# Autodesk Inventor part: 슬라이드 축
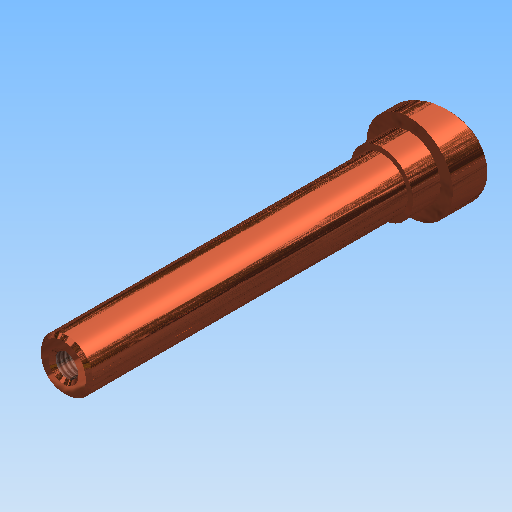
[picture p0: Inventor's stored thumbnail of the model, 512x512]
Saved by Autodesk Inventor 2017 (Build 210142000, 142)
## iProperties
Created: 2021-07
Part Number: 슬라이드 축
Document SubType Name: 모델링
Designer: mdu
Mass: 21.5729 g
Surface Area: 67.586 cm^2
Volume: 21.5729 cm^3
Density: 1 g/cm^3
Material: 일반
Appearance: 금속 1400F 열
변환 표준: STEP AP214IS
파일 이름: C:\Users\SeoGD\Desktop\?쒗뿕\異?stp
전처리기: Build: 253, Release: 2010 SP1 - Date: Wed 07/29/2009
전송 단위: 밀리미터
불확실성: 0.01
Author: mdu
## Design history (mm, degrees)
sketch "스케치1"
  geometry: L1 (0, 100)-(7.5, 100); L2 (7.5, 100)-(7.5, 0); L3 (7.5, 0)-(12.5, 0); L4 (12.5, 0)-(12.5, -17); L5 (12.5, -17)-(0, -17); L6 (0, -17)-(0, 100); 1 further point
  constraints: 12 end point, 2 parallel, 2 point on line, 1 perpendicular, 1 vertical
  dimensions: "d0" = 100 distance from line of L1 point (0, 0); "d1" = 15 diameter of L2 L6; "d2" = 25 diameter of L4 L6; "d3" = 17 distance of L3.end L4.end
revolve "회전1" sketch "스케치1" stored, may be unused: angle "d4" = 90 deg
sketch "스케치2"
  geometry: L1 (12.5, 0)-(12.5, -17) reference; L2 (-12.5, -17)-(12.5, -17) reference; L3 (-12.5, 0)-(-12.5, -17) reference; L4 (12.5, -5)-(-12.5, -11.699); L5 (-12.5, 0)-(12.5, 0) reference; 1 further point
  constraints: 2 end point, 2 point on line
  dimensions: "d5" = 75 deg angle of L1 L4; "d6" = 5 distance from line of L4.start L5
extrude "돌출1" cut sketch "스케치2" stored distance "d7" = 10; taper "d8" = 0 deg
chamfer "모따기1" distance "d9" = 1; stored, may be unused: second distance "d10" = 2, angle "d11" = 45 deg
fillet "모깎기1" dims "d12" = 0.5
hole "구멍1" diameter "d15" = 6.647; stored, may be unused: countersink angle "d19" = 90 deg, drill point angle "d21" = 118 deg; dims "d13" = 10, "d14" = 10, "d16" = 17, "d17" = 4, "d18" = 2, "d20" = 20
chamfer "모따기2" distance "d22" = 1; stored, may be unused: second distance "d23" = 2, angle "d24" = 45 deg
sketch "스케치3"
  geometry: C1 r 9 at (0, 0); 1 further point
  constraints: 1 centre point, 1 coincident
  dimensions: "d25" = 18 diameter of C1
extrude "돌출2" join sketch "스케치3" distance "d26" = 8; taper "d27" = 0 deg
node "솔리드1"
node "솔리드 본체"
node "곡면 본체"
node "솔리드2"
